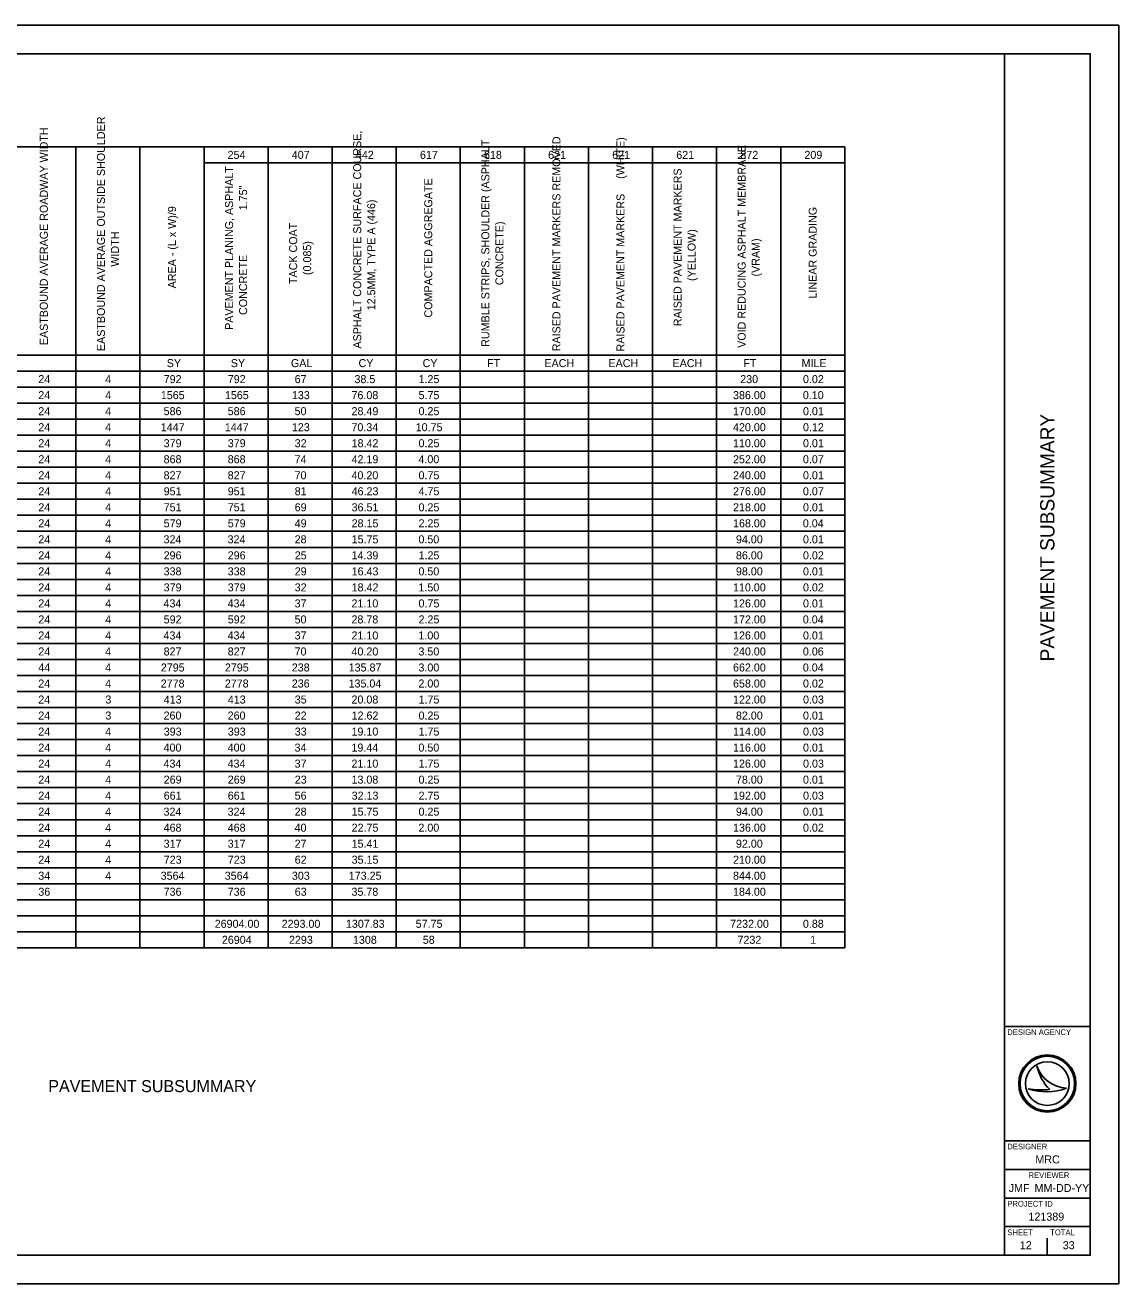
# Model space of a CAD drawing. Extents: x 0 to 34, y 0 to 22.
# Drawn here: x 14.88 to 34, y 0 to 22 of the extents above; entities that cross this region are included whole.
import ezdxf

# ---------------------------------------------------------------- set-up
doc = ezdxf.new("R2010")
doc.units = 0
for name, color, linetype in [('Default', 7, 'Continuous'), ('SH_Border', 7, 'Continuous'), ('SH_Cut_Line', 7, 'Continuous'), ('SH_Data', 7, 'Continuous'), ('SH_Text', 7, 'Continuous')]:
    doc.layers.add(name, color=color, linetype=linetype)

msp = doc.modelspace()

# ---------------------------------------------------------------- linework, layer by layer
at = {"layer": 'SH_Border'}
for p, q in [((32, 0.5), (32, 21.5)), ((32, 4.5), (33.5, 4.5)), ((32, 2.5), (33.5, 2.5)), ((32, 2), (33.5, 2)), ((32, 1.5), (33.5, 1.5)), ((32, 1), (33.5, 1))]:
    msp.add_line(p, q, dxfattribs=at)
msp.add_lwpolyline([(1.5, 21.5), (33.5, 21.5), (33.5, 0.5), (1.5, 0.5)], close=True, dxfattribs=at)
at = {"layer": 'SH_Cut_Line'}
msp.add_lwpolyline([(0, 0), (34, 0), (34, 22), (0, 22)], close=True, dxfattribs=at)
at = {"layer": 'SH_Data'}
for p, q in [((4.536, 19.873), (29.209, 19.873)), ((15.769, 19.873), (15.769, 5.873)), ((16.889, 19.873), (16.889, 5.873)), ((18.009, 19.873), (18.009, 19.593)), ((19.129, 19.873), (19.129, 5.873)), ((20.249, 19.873), (20.249, 5.873)), ((21.369, 19.873), (21.369, 16.233)), ((22.489, 19.873), (22.489, 5.873)), ((23.609, 19.873), (23.609, 5.873)), ((24.729, 19.873), (24.729, 5.873)), ((25.849, 19.873), (25.849, 5.873)), ((26.969, 19.873), (26.969, 5.873)), ((28.089, 19.873), (28.089, 16.233)), ((29.209, 19.873), (29.209, 5.873)), ((18.009, 19.593), (29.209, 19.593)), ((18.009, 19.593), (18.009, 5.873)), ((4.536, 16.233), (29.209, 16.233)), ((21.369, 16.233), (21.369, 15.953)), ((28.089, 16.233), (28.089, 15.953)), ((4.536, 15.953), (29.209, 15.953)), ((21.369, 15.953), (21.369, 5.873)), ((28.089, 15.953), (28.089, 5.873)), ((4.536, 15.673), (29.209, 15.673)), ((4.536, 15.393), (29.209, 15.393)), ((4.536, 15.113), (29.209, 15.113)), ((4.536, 14.833), (29.209, 14.833)), ((4.536, 14.553), (29.209, 14.553)), ((4.536, 14.273), (29.209, 14.273)), ((4.536, 13.993), (29.209, 13.993)), ((4.536, 13.713), (29.209, 13.713)), ((4.536, 13.433), (29.209, 13.433)), ((4.536, 13.153), (29.209, 13.153)), ((4.536, 12.873), (29.209, 12.873)), ((4.536, 12.593), (29.209, 12.593)), ((4.536, 12.313), (29.209, 12.313)), ((4.536, 12.033), (29.209, 12.033)), ((4.536, 11.753), (29.209, 11.753)), ((4.536, 11.473), (29.209, 11.473)), ((4.536, 11.193), (29.209, 11.193)), ((4.536, 10.913), (29.209, 10.913)), ((4.536, 10.633), (29.209, 10.633)), ((4.536, 10.353), (29.209, 10.353)), ((4.536, 10.073), (29.209, 10.073)), ((4.536, 9.793), (29.209, 9.793)), ((4.536, 9.513), (29.209, 9.513)), ((4.536, 9.233), (29.209, 9.233)), ((4.536, 8.953), (29.209, 8.953)), ((4.536, 8.673), (29.209, 8.673)), ((4.536, 8.393), (29.209, 8.393)), ((4.536, 8.113), (29.209, 8.113)), ((4.536, 7.833), (29.209, 7.833)), ((4.536, 7.553), (29.209, 7.553)), ((4.536, 7.273), (29.209, 7.273)), ((4.536, 6.993), (29.209, 6.993)), ((4.536, 6.713), (29.209, 6.713)), ((4.536, 6.433), (29.209, 6.433)), ((4.536, 6.153), (29.209, 6.153)), ((4.536, 5.873), (29.209, 5.873)), ((32.567, 3.81), (32.567, 3.81)), ((32.417, 3.41), (32.417, 3.41)), ((32.75, 3.5), (32.75, 3.5)), ((33.087, 3.419), (33.087, 3.419)), ((32.375, 0.675), (32.375, 0.675)), ((32.75, 0.5), (32.75, 0.8))]:
    msp.add_line(p, q, dxfattribs=at)
for radius in [0.5, 0.477, 0.477, 0.382]:
    msp.add_circle((32.75, 3.5), radius, dxfattribs=at)
for centre, radius, start, end in [((33.116, 3.998), 0.58, 198.9257, 198.9319), ((33.347, 3.97), 0.796, 191.6379, 191.6421), ((33.116, 3.998), 0.58, 198.9319, 267.1657), ((33.347, 3.97), 0.796, 191.6421, 226.0947), ((32.739, 4.37), 1.013, 251.4576, 290.0832), ((32.648, 4.654), 1.266, 259.4964, 259.4995), ((32.739, 4.37), 1.013, 251.4527, 251.4576), ((32.648, 4.654), 1.266, 259.4995, 276.6672)]:
    msp.add_arc(centre, radius, start, end, dxfattribs=at)

# ---------------------------------------------------------------- texts
at = {"layer": 'Default'}
msp.add_text('PAVEMENT SUBSUMMARY', height=0.21, dxfattribs=at).set_placement((15.287, 3.351))
at = {"layer": 'SH_Data'}
msp.add_text('PAVEMENT SUBSUMMARY', height=0.25, rotation=90, dxfattribs=at).set_placement((32.875, 10.879))
for s, height, p in [('DESIGN AGENCY', 0.1, (32.05, 4.35)), ('DESIGNER', 0.1, (32.05, 2.35)), ('MRC', 0.14, (32.541, 2.105)), ('REVIEWER', 0.1, (32.422, 1.85)), ('JMF', 0.14, (32.075, 1.605)), ('MM-DD-YY', 0.14, (32.527, 1.605)), ('PROJECT ID', 0.1, (32.05, 1.35)), ('121389', 0.14, (32.42, 1.105)), ('SHEET', 0.1, (32.05, 0.85)), ('TOTAL', 0.1, (32.8, 0.85)), ('12', 0.14, (32.269, 0.605)), ('33', 0.14, (33.02, 0.605))]:
    msp.add_text(s, height=height, dxfattribs=at).set_placement(p)
at = {"layer": 'SH_Text'}
for s, p in [('EASTBOUND AVERAGE OUTSIDE SHOULDER ', (16.277, 16.304)), ('EASTBOUND AVERAGE ROADWAY WIDTH', (15.279, 16.407)), ('ASPHALT CONCRETE SURFACE COURSE, ', (20.757, 16.348)), ('RAISED PAVEMENT MARKERS REMOVED', (24.239, 16.3)), ('RAISED PAVEMENT MARKERS     (WHITE)', (25.359, 16.297)), ('RUMBLE STRIPS, SHOULDER (ASPHALT ', (22.997, 16.378)), ('VOID REDUCING ASPHALT MEMBRANE ', (27.477, 16.36)), ('PAVEMENT PLANING, ASPHALT ', (18.517, 16.674)), ('RAISED PAVEMENT MARKERS     ', (26.357, 16.739)), ('CONCRETE               1.75"', (18.762, 16.935)), ('COMPACTED AGGREGATE', (21.999, 16.889)), ('12.5MM, TYPE A (446)', (21.002, 17.017)), ('AREA - (L x W)/9', (17.519, 17.4)), ('LINEAR GRADING', (28.719, 17.222)), ('TACK COAT                                                           ', (19.637, 17.475)), ('CONCRETE)', (23.242, 17.456)), ('WIDTH', (16.522, 17.778)), ('(YELLOW)', (26.602, 17.529)), ('(VRAM)', (27.722, 17.607)), ('(0.085)', (19.882, 17.633))]:
    msp.add_text(s, height=0.14, rotation=90, dxfattribs=at).set_placement(p)
for s, p in [('254', (18.421, 19.663)), ('407', (19.543, 19.663)), ('442', (20.664, 19.663)), ('617', (21.783, 19.663)), ('618', (22.903, 19.663)), ('621', (24.024, 19.663)), ('621', (25.144, 19.663)), ('621', (26.264, 19.663)), ('872', (27.384, 19.663)), ('209', (28.504, 19.663)), ('SY', (17.358, 16.023)), ('SY', (18.478, 16.023)), ('GAL', (19.528, 16.023)), ('CY', (20.71, 16.023)), ('CY', (21.83, 16.023)), ('FT', (22.956, 16.023)), ('EACH', (23.959, 16.023)), ('EACH', (25.079, 16.023)), ('EACH', (26.199, 16.023)), ('FT', (27.436, 16.023)), ('MILE', (28.455, 16.023)), ('24', (15.112, 15.743)), ('4', (16.282, 15.743)), ('792', (17.304, 15.743)), ('792', (18.424, 15.743)), ('67', (19.593, 15.743)), ('38.5', (20.639, 15.743)), ('1.25', (21.759, 15.743)), ('230', (27.382, 15.743)), ('0.02', (28.479, 15.743)), ('24', (15.112, 15.463)), ('4', (16.282, 15.463)), ('1565', (17.254, 15.463)), ('1565', (18.374, 15.463)), ('133', (19.545, 15.463)), ('76.08', (20.587, 15.463)), ('5.75', (21.759, 15.463)), ('386.00', (27.256, 15.463)), ('0.10', (28.477, 15.463)), ('24', (15.112, 15.183)), ('4', (16.282, 15.183)), ('586', (17.303, 15.183)), ('586', (18.423, 15.183)), ('50', (19.592, 15.183)), ('28.49', (20.588, 15.183)), ('0.25', (21.759, 15.183)), ('170.00', (27.256, 15.183)), ('0.01', (28.479, 15.183)), ('24', (15.112, 14.903)), ('4', (16.282, 14.903)), ('1447', (17.253, 14.903)), ('1447', (18.373, 14.903)), ('123', (19.545, 14.903)), ('70.34', (20.586, 14.903)), ('10.75', (21.709, 14.903)), ('420.00', (27.256, 14.903)), ('0.12', (28.479, 14.903)), ('24', (15.112, 14.623)), ('4', (16.282, 14.623)), ('379', (17.304, 14.623)), ('379', (18.424, 14.623)), ('32', (19.594, 14.623)), ('18.42', (20.589, 14.623)), ('0.25', (21.759, 14.623)), ('110.00', (27.256, 14.623)), ('0.01', (28.479, 14.623)), ('24', (15.112, 14.343)), ('4', (16.282, 14.343)), ('868', (17.303, 14.343)), ('868', (18.423, 14.343)), ('74', (19.592, 14.343)), ('42.19', (20.588, 14.343)), ('4.00', (21.757, 14.343)), ('252.00', (27.256, 14.343)), ('0.07', (28.478, 14.343)), ('24', (15.112, 14.063)), ('4', (16.282, 14.063)), ('827', (17.303, 14.063)), ('827', (18.423, 14.063)), ('70', (19.592, 14.063)), ('40.20', (20.587, 14.063)), ('0.75', (21.759, 14.063)), ('240.00', (27.256, 14.063)), ('0.01', (28.479, 14.063)), ('24', (15.112, 13.783)), ('4', (16.282, 13.783)), ('951', (17.304, 13.783)), ('951', (18.424, 13.783)), ('81', (19.594, 13.783)), ('46.23', (20.589, 13.783)), ('4.75', (21.759, 13.783)), ('276.00', (27.256, 13.783)), ('0.07', (28.478, 13.783)), ('24', (15.112, 13.503)), ('4', (16.282, 13.503)), ('751', (17.304, 13.503)), ('751', (18.424, 13.503)), ('69', (19.594, 13.503)), ('36.51', (20.589, 13.503)), ('0.25', (21.759, 13.503)), ('218.00', (27.256, 13.503)), ('0.01', (28.479, 13.503)), ('24', (15.112, 13.223)), ('4', (16.282, 13.223)), ('579', (17.304, 13.223)), ('579', (18.424, 13.223)), ('49', (19.594, 13.223)), ('28.15', (20.589, 13.223)), ('2.25', (21.759, 13.223)), ('168.00', (27.256, 13.223)), ('0.04', (28.476, 13.223)), ('24', (15.112, 12.943)), ('4', (16.282, 12.943)), ('324', (17.301, 12.943)), ('324', (18.421, 12.943)), ('28', (19.593, 12.943)), ('15.75', (20.589, 12.943)), ('0.50', (21.757, 12.943)), ('94.00', (27.307, 12.943)), ('0.01', (28.479, 12.943)), ('24', (15.112, 12.663)), ('4', (16.282, 12.663)), ('296', (17.303, 12.663)), ('296', (18.423, 12.663)), ('25', (19.595, 12.663)), ('14.39', (20.588, 12.663)), ('1.25', (21.759, 12.663)), ('86.00', (27.307, 12.663)), ('0.02', (28.479, 12.663)), ('24', (15.112, 12.383)), ('4', (16.282, 12.383)), ('338', (17.303, 12.383)), ('338', (18.423, 12.383)), ('29', (19.594, 12.383)), ('16.43', (20.589, 12.383)), ('0.50', (21.757, 12.383)), ('98.00', (27.307, 12.383)), ('0.01', (28.479, 12.383)), ('24', (15.112, 12.103)), ('4', (16.282, 12.103)), ('379', (17.304, 12.103)), ('379', (18.424, 12.103)), ('32', (19.594, 12.103)), ('18.42', (20.589, 12.103)), ('1.50', (21.757, 12.103)), ('110.00', (27.256, 12.103)), ('0.02', (28.479, 12.103)), ('24', (15.112, 11.823)), ('4', (16.282, 11.823)), ('434', (17.301, 11.823)), ('434', (18.421, 11.823)), ('37', (19.593, 11.823)), ('21.10', (20.587, 11.823)), ('0.75', (21.759, 11.823)), ('126.00', (27.256, 11.823)), ('0.01', (28.479, 11.823)), ('24', (15.112, 11.543)), ('4', (16.282, 11.543)), ('592', (17.304, 11.543)), ('592', (18.424, 11.543)), ('50', (19.592, 11.543)), ('28.78', (20.587, 11.543)), ('2.25', (21.759, 11.543)), ('172.00', (27.256, 11.543)), ('0.04', (28.476, 11.543)), ('24', (15.112, 11.263)), ('4', (16.282, 11.263)), ('434', (17.301, 11.263)), ('434', (18.421, 11.263)), ('37', (19.593, 11.263)), ('21.10', (20.587, 11.263)), ('1.00', (21.757, 11.263)), ('126.00', (27.256, 11.263)), ('0.01', (28.479, 11.263)), ('24', (15.112, 10.983)), ('4', (16.282, 10.983)), ('827', (17.303, 10.983)), ('827', (18.423, 10.983)), ('70', (19.592, 10.983)), ('40.20', (20.587, 10.983)), ('3.50', (21.757, 10.983)), ('240.00', (27.256, 10.983)), ('0.06', (28.477, 10.983)), ('44', (15.112, 10.703)), ('4', (16.282, 10.703)), ('2795', (17.254, 10.703)), ('2795', (18.374, 10.703)), ('238', (19.543, 10.703)), ('135.87', (20.538, 10.703)), ('3.00', (21.757, 10.703)), ('662.00', (27.256, 10.703)), ('0.04', (28.476, 10.703)), ('24', (15.112, 10.423)), ('4', (16.282, 10.423)), ('2778', (17.252, 10.423)), ('2778', (18.372, 10.423)), ('236', (19.543, 10.423)), ('135.04', (20.536, 10.423)), ('2.00', (21.757, 10.423)), ('658.00', (27.256, 10.423)), ('0.02', (28.479, 10.423)), ('24', (15.112, 10.143)), ('3', (16.285, 10.143)), ('413', (17.305, 10.143)), ('413', (18.425, 10.143)), ('35', (19.595, 10.143)), ('20.08', (20.587, 10.143)), ('1.75', (21.759, 10.143)), ('122.00', (27.256, 10.143)), ('0.03', (28.48, 10.143)), ('24', (15.112, 9.863)), ('3', (16.285, 9.863)), ('260', (17.302, 9.863)), ('260', (18.422, 9.863)), ('22', (19.594, 9.863)), ('12.62', (20.589, 9.863)), ('0.25', (21.759, 9.863)), ('82.00', (27.307, 9.863)), ('0.01', (28.479, 9.863)), ('24', (15.112, 9.583)), ('4', (16.282, 9.583)), ('393', (17.305, 9.583)), ('393', (18.425, 9.583)), ('33', (19.595, 9.583)), ('19.10', (20.587, 9.583)), ('1.75', (21.759, 9.583)), ('114.00', (27.256, 9.583)), ('0.03', (28.48, 9.583)), ('24', (15.112, 9.303)), ('4', (16.282, 9.303)), ('400', (17.302, 9.303)), ('400', (18.422, 9.303)), ('34', (19.592, 9.303)), ('19.44', (20.586, 9.303)), ('0.50', (21.757, 9.303)), ('116.00', (27.256, 9.303)), ('0.01', (28.479, 9.303)), ('24', (15.112, 9.023)), ('4', (16.282, 9.023)), ('434', (17.301, 9.023)), ('434', (18.421, 9.023)), ('37', (19.593, 9.023)), ('21.10', (20.587, 9.023)), ('1.75', (21.759, 9.023)), ('126.00', (27.256, 9.023)), ('0.03', (28.48, 9.023)), ('24', (15.112, 8.743)), ('4', (16.282, 8.743)), ('269', (17.304, 8.743)), ('269', (18.424, 8.743)), ('23', (19.595, 8.743)), ('13.08', (20.587, 8.743)), ('0.25', (21.759, 8.743)), ('78.00', (27.307, 8.743)), ('0.01', (28.479, 8.743)), ('24', (15.112, 8.463)), ('4', (16.282, 8.463)), ('661', (17.304, 8.463)), ('661', (18.424, 8.463)), ('56', (19.593, 8.463)), ('32.13', (20.589, 8.463)), ('2.75', (21.759, 8.463)), ('192.00', (27.256, 8.463)), ('0.03', (28.48, 8.463)), ('24', (15.112, 8.183)), ('4', (16.282, 8.183)), ('324', (17.301, 8.183)), ('324', (18.421, 8.183)), ('28', (19.593, 8.183)), ('15.75', (20.589, 8.183)), ('0.25', (21.759, 8.183)), ('94.00', (27.307, 8.183)), ('0.01', (28.479, 8.183)), ('24', (15.112, 7.903)), ('4', (16.282, 7.903)), ('468', (17.303, 7.903)), ('468', (18.423, 7.903)), ('40', (19.592, 7.903)), ('22.75', (20.589, 7.903)), ('2.00', (21.757, 7.903)), ('136.00', (27.256, 7.903)), ('0.02', (28.479, 7.903)), ('24', (15.112, 7.623)), ('4', (16.282, 7.623)), ('317', (17.303, 7.623)), ('317', (18.423, 7.623)), ('27', (19.593, 7.623)), ('15.41', (20.589, 7.623)), ('92.00', (27.307, 7.623)), ('24', (15.112, 7.343)), ('4', (16.282, 7.343)), ('723', (17.305, 7.343)), ('723', (18.425, 7.343)), ('62', (19.594, 7.343)), ('35.15', (20.589, 7.343)), ('210.00', (27.256, 7.343)), ('34', (15.112, 7.063)), ('4', (16.282, 7.063)), ('3564', (17.251, 7.063)), ('3564', (18.371, 7.063)), ('303', (19.545, 7.063)), ('173.25', (20.539, 7.063)), ('844.00', (27.256, 7.063)), ('36', (15.113, 6.783)), ('736', (17.303, 6.783)), ('736', (18.423, 6.783)), ('63', (19.595, 6.783)), ('35.78', (20.587, 6.783)), ('184.00', (27.256, 6.783)), ('26904.00', (18.196, 6.223)), ('2293.00', (19.366, 6.223)), ('1307.83', (20.489, 6.223)), ('57.75', (21.709, 6.223)), ('7232.00', (27.206, 6.223)), ('0.88', (28.478, 6.223)), ('26904', (18.321, 5.943)), ('2293', (19.494, 5.943)), ('1308', (20.612, 5.943)), ('58', (21.833, 5.943)), ('7232', (27.334, 5.943)), ('1', (28.605, 5.943))]:
    msp.add_text(s, height=0.14, dxfattribs=at).set_placement(p)

doc.saveas('drawing.dxf')
